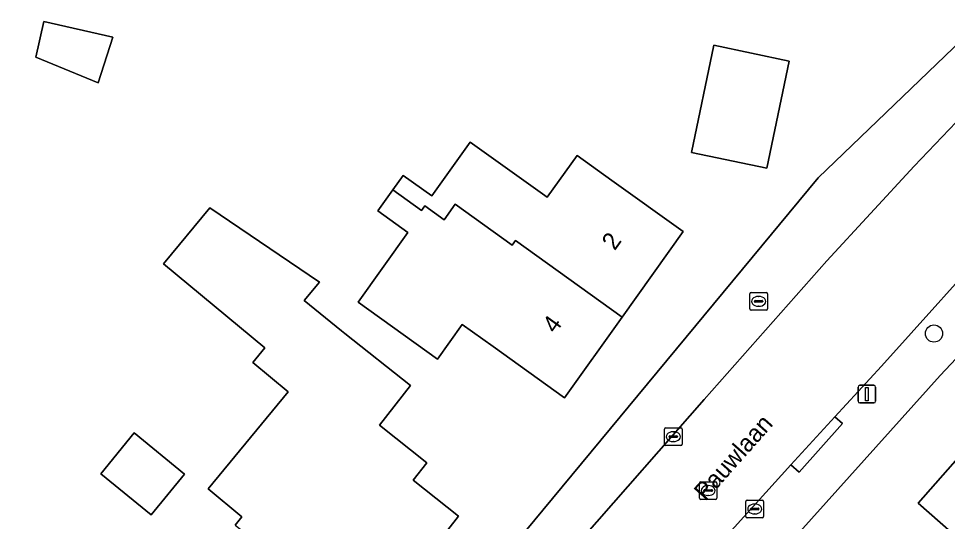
# Model space of a CAD drawing. Extents: x 161772 to 163126, y 383092 to 383917.
# Drawn here: x 162481.4 to 162534.3, y 383587.6 to 383616.2 of the extents above; entities that cross this region are included whole.
import ezdxf

# ---------------------------------------------------------------- set-up
doc = ezdxf.new("R2010")
doc.units = 0
for name, color, linetype in [('IMGEO_Boom', 7, 'Continuous'), ('IMGEO_Brandkraan', 7, 'Continuous'), ('IMGEO_Erf', 7, 'Continuous'), ('IMGEO_Kolk', 7, 'Continuous'), ('IMGEO_Lichtmast', 7, 'Continuous'), ('IMGEO_Openbare_ruimte_label', 7, 'Continuous'), ('IMGEO_Pand', 7, 'Continuous'), ('IMGEO_Pand_nummerreeks', 7, 'Continuous'), ('IMGEO_Rijbaan_lokaal_open', 7, 'Continuous'), ('IMGEO_Rioolput', 7, 'Continuous'), ('IMGEO_Voetpad_open', 7, 'Continuous')]:
    doc.layers.add(name, color=color, linetype=linetype)

msp = doc.modelspace()

# ---------------------------------------------------------------- linework, layer by layer
at = {"layer": 'IMGEO_Boom'}
msp.add_circle((162533.543, 383598.255), 0.489, dxfattribs=at)
at = {"layer": 'IMGEO_Brandkraan'}
for p, q in [((162523.058, 383599.658), (162523.058, 383600.51)), ((162523.133, 383600.584), (162523.985, 383600.584)), ((162523.317, 383600.078), (162523.317, 383600.09)), ((162523.36, 383600.127), (162523.758, 383600.127)), ((162523.546, 383600.364), (162523.571, 383600.364)), ((162523.801, 383600.09), (162523.801, 383600.078)), ((162524.059, 383600.51), (162524.059, 383599.658)), ((162523.985, 383599.584), (162523.133, 383599.584)), ((162523.755, 383600.041), (162523.357, 383600.041)), ((162523.569, 383599.804), (162523.544, 383599.804))]:
    msp.add_line(p, q, dxfattribs=at)
for points in [[(162523.058, 383599.658), (162523.058, 383600.51)], [(162523.133, 383600.584), (162523.985, 383600.584)], [(162524.059, 383600.51), (162524.059, 383599.658)], [(162523.985, 383599.584), (162523.133, 383599.584)]]:
    msp.add_lwpolyline(points, dxfattribs=at)
for centre, radius, start, end in [((162523.135, 383600.508), 0.0765, 91.552, 178.448), ((162523.135, 383600.508), 0.0765, 91.552, 178.448), ((162523.357, 383600.087), 0.0403, 85.8775, 175.7526), ((162523.354, 383600.077), 0.0366, 178.938, 274.7102), ((162523.758, 383600.084), 0.043, 264.8664, 352.4533), ((162523.762, 383600.089), 0.0386, 1.7309, 96.639), ((162523.983, 383600.508), 0.0765, 1.552, 88.448), ((162523.983, 383600.508), 0.0765, 1.552, 88.448), ((162523.135, 383599.66), 0.0765, 181.552, 268.448), ((162523.135, 383599.66), 0.0765, 181.552, 268.448), ((162523.983, 383599.66), 0.0765, 271.552, 358.448), ((162523.983, 383599.66), 0.0765, 271.552, 358.448)]:
    msp.add_arc(centre, radius, start, end, dxfattribs=at)
for centre, major_axis, ratio, start_param, end_param in [((162523.545, 383600.084), (-0.387, 0.002), 0.722429, 4.712389, 7.853982), ((162523.57, 383600.084), (-0.39, 0.002), 0.717154, 1.570796, 4.712389)]:
    msp.add_ellipse(centre, major_axis=major_axis, ratio=ratio, start_param=start_param, end_param=end_param, dxfattribs=at)
at = {"layer": 'IMGEO_Erf'}
for points in [[(162462.704, 383536.779), (162483.744, 383554.98), (162500, 383574.599), (162526.947, 383607.122), (162543.804, 383623.317), (162548.918, 383628.126), (162539.791, 383641.093), (162527.133, 383641.683), (162527.105, 383641.456), (162500, 383642.583), (162442.25, 383644.984), (162375.184, 383528.714), (162418.191, 383500), (162425.357, 383495.215)], [(162493.744, 383587.36), (162494.132, 383587.828), (162492.201, 383589.429), (162496.763, 383594.932), (162494.746, 383596.605), (162495.432, 383597.433), (162489.661, 383602.217), (162492.309, 383605.412), (162498.544, 383601.187), (162497.67, 383600.132), (162499.797, 383598.417), (162500, 383598.256), (162503.741, 383595.297), (162501.958, 383593.04), (162504.664, 383590.902), (162503.885, 383589.916), (162506.472, 383587.872), (162501.403, 383581.38)], [(162539.703, 383602.034), (162533.89, 383595.873), (162525.907, 383586.964), (162518.786, 383578.702), (162510.666, 383568.842), (162501.518, 383557.733), (162500, 383555.89), (162492.693, 383547.017)]]:
    msp.add_lwpolyline(points, dxfattribs=at)
for points in [[(162482.391, 383613.973), (162482.841, 383616.012), (162486.783, 383615.11), (162485.937, 383612.514)], [(162519.734, 383608.563), (162521.016, 383614.659), (162525.306, 383613.757), (162524.024, 383607.661)], [(162502.72, 383606.437), (162503.306, 383607.254), (162504.939, 383606.083), (162507.133, 383609.142), (162511.507, 383606.005), (162513.219, 383608.39), (162515.204, 383606.968), (162519.268, 383604.056), (162515.786, 383599.195), (162512.495, 383594.6), (162508.431, 383597.511), (162506.677, 383598.767), (162505.271, 383596.805), (162500.747, 383600.048), (162503.586, 383604.008), (162501.864, 383605.243)], [(162544.222, 383584.846), (162541.032, 383581.223), (162536.404, 383585.298), (162532.651, 383588.602), (162539.681, 383596.585), (162543.434, 383593.281), (162548.075, 383589.194), (162546.474, 383587.375), (162546.712, 383586.669), (162544.973, 383584.695)], [(162486.087, 383590.277), (162487.992, 383592.607), (162490.859, 383590.263), (162488.955, 383587.933)]]:
    msp.add_lwpolyline(points, close=True, dxfattribs=at)
at = {"layer": 'IMGEO_Kolk'}
for p, q in [((162518.198, 383591.959), (162518.198, 383592.811)), ((162518.273, 383592.885), (162519.125, 383592.885)), ((162519.199, 383592.811), (162519.199, 383591.959)), ((162518.457, 383592.379), (162518.457, 383592.391)), ((162518.895, 383592.342), (162518.497, 383592.342)), ((162518.5, 383592.428), (162518.898, 383592.428)), ((162518.686, 383592.665), (162518.711, 383592.665)), ((162518.941, 383592.391), (162518.941, 383592.379)), ((162519.125, 383591.885), (162518.273, 383591.885)), ((162518.709, 383592.105), (162518.684, 383592.105)), ((162522.835, 383587.848), (162522.835, 383588.7)), ((162522.91, 383588.774), (162523.762, 383588.774)), ((162523.323, 383588.554), (162523.348, 383588.554)), ((162523.836, 383588.7), (162523.836, 383587.848)), ((162523.094, 383588.268), (162523.094, 383588.28)), ((162523.532, 383588.231), (162523.134, 383588.231)), ((162523.137, 383588.317), (162523.535, 383588.317)), ((162523.346, 383587.994), (162523.321, 383587.994)), ((162523.578, 383588.28), (162523.578, 383588.268)), ((162523.762, 383587.774), (162522.91, 383587.774))]:
    msp.add_line(p, q, dxfattribs=at)
for points in [[(162518.198, 383591.959), (162518.198, 383592.811)], [(162518.273, 383592.885), (162519.125, 383592.885)], [(162519.199, 383592.811), (162519.199, 383591.959)], [(162519.125, 383591.885), (162518.273, 383591.885)], [(162522.835, 383587.848), (162522.835, 383588.7)], [(162522.91, 383588.774), (162523.762, 383588.774)], [(162523.836, 383588.7), (162523.836, 383587.848)], [(162523.762, 383587.774), (162522.91, 383587.774)]]:
    msp.add_lwpolyline(points, dxfattribs=at)
for centre, radius, start, end in [((162518.275, 383592.809), 0.0765, 91.552, 178.448), ((162518.275, 383592.809), 0.0765, 91.552, 178.448), ((162519.123, 383592.809), 0.0765, 1.552, 88.448), ((162519.123, 383592.809), 0.0765, 1.552, 88.448), ((162518.497, 383592.388), 0.0403, 85.8775, 175.7526), ((162518.494, 383592.378), 0.0366, 178.938, 274.7102), ((162518.898, 383592.385), 0.043, 264.8664, 352.4533), ((162518.902, 383592.39), 0.0386, 1.7309, 96.639), ((162518.275, 383591.961), 0.0765, 181.552, 268.448), ((162518.275, 383591.961), 0.0765, 181.552, 268.448), ((162519.123, 383591.961), 0.0765, 271.552, 358.448), ((162519.123, 383591.961), 0.0765, 271.552, 358.448), ((162522.912, 383588.698), 0.0765, 91.552, 178.448), ((162522.912, 383588.698), 0.0765, 91.552, 178.448), ((162523.76, 383588.698), 0.0765, 1.552, 88.448), ((162523.76, 383588.698), 0.0765, 1.552, 88.448), ((162523.134, 383588.277), 0.0403, 85.8775, 175.7526), ((162523.131, 383588.267), 0.0366, 178.938, 274.7102), ((162523.535, 383588.274), 0.043, 264.8664, 352.4533), ((162523.539, 383588.279), 0.0386, 1.7309, 96.639), ((162522.912, 383587.85), 0.0765, 181.552, 268.448), ((162522.912, 383587.85), 0.0765, 181.552, 268.448), ((162523.76, 383587.85), 0.0765, 271.552, 358.448), ((162523.76, 383587.85), 0.0765, 271.552, 358.448)]:
    msp.add_arc(centre, radius, start, end, dxfattribs=at)
for centre, major_axis, ratio, start_param, end_param in [((162518.685, 383592.385), (-0.387, 0.002), 0.722429, 4.712389, 7.853982), ((162518.71, 383592.385), (-0.39, 0.002), 0.717154, 1.570796, 4.712389), ((162523.322, 383588.274), (-0.387, 0.002), 0.722429, 4.712389, 7.853982), ((162523.347, 383588.274), (-0.39, 0.002), 0.717154, 1.570796, 4.712389)]:
    msp.add_ellipse(centre, major_axis=major_axis, ratio=ratio, start_param=start_param, end_param=end_param, dxfattribs=at)
at = {"layer": 'IMGEO_Lichtmast'}
for p, q in [((162529.226, 383594.41), (162529.226, 383595.21)), ((162529.226, 383595.21), (162529.226, 383594.41)), ((162529.326, 383595.31), (162530.116, 383595.31)), ((162530.116, 383595.31), (162529.326, 383595.31)), ((162530.216, 383595.21), (162530.216, 383594.41)), ((162530.216, 383594.41), (162530.216, 383595.21)), ((162530.116, 383594.31), (162529.326, 383594.31)), ((162529.326, 383594.31), (162530.116, 383594.31))]:
    msp.add_line(p, q, dxfattribs=at)
msp.add_lwpolyline([(162529.646, 383595.185), (162529.796, 383595.185), (162529.796, 383594.435), (162529.646, 383594.435), (162529.646, 383595.185)], dxfattribs=at)
for centre, start, end in [((162529.326, 383595.21), 90, 180), ((162529.326, 383595.21), 90, 180), ((162530.116, 383595.21), 0, 90), ((162530.116, 383595.21), 360, 90), ((162529.326, 383594.41), 180, 270), ((162529.326, 383594.41), 180, 270), ((162530.116, 383594.41), 270, 0), ((162530.116, 383594.41), 270, 0)]:
    msp.add_arc(centre, 0.1, start, end, dxfattribs=at)
at = {"layer": 'IMGEO_Pand'}
for points in [[(162482.391, 383613.973), (162485.937, 383612.514), (162486.783, 383615.11), (162482.841, 383616.012)], [(162524.024, 383607.661), (162525.306, 383613.757), (162521.016, 383614.659), (162519.734, 383608.563)], [(162502.72, 383606.437), (162504.356, 383605.265), (162504.544, 383605.528), (162505.651, 383604.734), (162506.277, 383605.609), (162509.517, 383603.287), (162509.705, 383603.55), (162515.786, 383599.195), (162519.268, 383604.056), (162515.204, 383606.968), (162513.219, 383608.39), (162511.507, 383606.005), (162507.133, 383609.142), (162504.939, 383606.083), (162503.306, 383607.254)], [(162502.72, 383606.437), (162501.864, 383605.243), (162503.586, 383604.008), (162500.747, 383600.048), (162505.271, 383596.805), (162506.677, 383598.767), (162508.431, 383597.511), (162512.495, 383594.6), (162515.786, 383599.195), (162509.705, 383603.55), (162509.517, 383603.287), (162506.277, 383605.609), (162505.651, 383604.734), (162504.544, 383605.528), (162504.356, 383605.265)], [(162504.664, 383590.902), (162501.958, 383593.04), (162503.741, 383595.297), (162500, 383598.256), (162499.797, 383598.417), (162497.67, 383600.132), (162498.544, 383601.187), (162492.309, 383605.412), (162489.661, 383602.217), (162495.432, 383597.433), (162494.746, 383596.605), (162496.763, 383594.932), (162492.201, 383589.429), (162494.132, 383587.828), (162493.744, 383587.36), (162494.073, 383587.101), (162500, 383582.475), (162501.06, 383581.651), (162501.403, 383581.38), (162506.472, 383587.872), (162503.885, 383589.916)], [(162541.032, 383581.223), (162544.222, 383584.846), (162544.973, 383584.695), (162546.712, 383586.669), (162546.474, 383587.375), (162548.075, 383589.194), (162543.434, 383593.281), (162539.681, 383596.585), (162532.651, 383588.602), (162536.404, 383585.298)], [(162490.859, 383590.263), (162487.992, 383592.607), (162486.087, 383590.277), (162488.955, 383587.933)]]:
    msp.add_lwpolyline(points, close=True, dxfattribs=at)
at = {"layer": 'IMGEO_Rijbaan_lokaal_open'}
msp.add_lwpolyline([(162537.203, 383612.786), (162532.418, 383607.776), (162527.435, 383602.384), (162520.458, 383594.506), (162513.52, 383586.607), (162511.095, 383583.664), (162507.749, 383579.508), (162503.132, 383574.038), (162499.96, 383570.06), (162490.713, 383558.838), (162488.243, 383555.841), (162487.591, 383555.051), (162492.315, 383551.109), (162499.866, 383560.331), (162506.576, 383568.47), (162512.205, 383575.261), (162517.639, 383581.965), (162521.297, 383586.253), (162525.402, 383590.777), (162527.89, 383593.519), (162530.565, 383596.403), (162537.488, 383604.096)], dxfattribs=at)
at = {"layer": 'IMGEO_Rioolput'}
for p, q in [((162520.184, 383588.895), (162520.184, 383589.747)), ((162520.259, 383589.821), (162521.111, 383589.821)), ((162520.672, 383589.601), (162520.697, 383589.601)), ((162521.185, 383589.747), (162521.185, 383588.895)), ((162520.443, 383589.315), (162520.443, 383589.327)), ((162520.881, 383589.278), (162520.483, 383589.278)), ((162520.486, 383589.364), (162520.884, 383589.364)), ((162520.695, 383589.041), (162520.67, 383589.041)), ((162520.927, 383589.327), (162520.927, 383589.315)), ((162521.111, 383588.821), (162520.259, 383588.821))]:
    msp.add_line(p, q, dxfattribs=at)
for points in [[(162520.184, 383588.895), (162520.184, 383589.747)], [(162520.259, 383589.821), (162521.111, 383589.821)], [(162521.185, 383589.747), (162521.185, 383588.895)], [(162521.111, 383588.821), (162520.259, 383588.821)]]:
    msp.add_lwpolyline(points, dxfattribs=at)
for centre, radius, start, end in [((162520.261, 383589.745), 0.0765, 91.552, 178.448), ((162520.261, 383589.745), 0.0765, 91.552, 178.448), ((162521.109, 383589.745), 0.0765, 1.552, 88.448), ((162521.109, 383589.745), 0.0765, 1.552, 88.448), ((162520.483, 383589.324), 0.0403, 85.8775, 175.7526), ((162520.48, 383589.314), 0.0366, 178.938, 274.7102), ((162520.884, 383589.321), 0.043, 264.8664, 352.4533), ((162520.888, 383589.326), 0.0386, 1.7309, 96.639), ((162520.261, 383588.897), 0.0765, 181.552, 268.448), ((162520.261, 383588.897), 0.0765, 181.552, 268.448), ((162521.109, 383588.897), 0.0765, 271.552, 358.448), ((162521.109, 383588.897), 0.0765, 271.552, 358.448)]:
    msp.add_arc(centre, radius, start, end, dxfattribs=at)
for centre, major_axis, ratio, start_param, end_param in [((162520.671, 383589.321), (-0.387, 0.002), 0.722429, 4.712389, 7.853982), ((162520.696, 383589.321), (-0.39, 0.002), 0.717154, 1.570796, 4.712389)]:
    msp.add_ellipse(centre, major_axis=major_axis, ratio=ratio, start_param=start_param, end_param=end_param, dxfattribs=at)
at = {"layer": 'IMGEO_Voetpad_open'}
for points in [[(162549.66, 383629.858), (162548.918, 383628.126), (162543.804, 383623.317), (162526.947, 383607.122), (162500, 383574.599), (162483.744, 383554.98), (162462.704, 383536.779), (162467.807, 383530.859), (162432.045, 383500), (162426.613, 383495.312), (162428.778, 383494.029), (162435.72, 383500), (162437.045, 383501.14), (162437.192, 383501.282), (162438.691, 383502.574), (162438.438, 383502.865), (162441.394, 383505.425), (162441.654, 383505.126), (162443.112, 383506.379), (162469.395, 383528.971)], [(162468.577, 383537.721), (162484.483, 383551.467), (162485.735, 383552.822), (162487.591, 383555.051), (162488.243, 383555.841), (162487.915, 383556.108), (162490.371, 383559.116), (162490.713, 383558.838), (162499.96, 383570.06), (162503.132, 383574.038), (162507.749, 383579.508), (162511.095, 383583.664), (162510.859, 383583.859), (162513.286, 383586.801), (162513.52, 383586.607), (162520.458, 383594.506), (162527.435, 383602.384), (162532.418, 383607.776), (162537.203, 383612.786), (162540.103, 383615.776), (162538.984, 383617.258), (162540.462, 383618.813), (162542.308, 383616.755)], [(162497.729, 383541.518), (162492.693, 383547.017), (162500, 383555.89), (162501.518, 383557.733), (162510.666, 383568.842), (162518.786, 383578.702), (162525.907, 383586.964), (162533.89, 383595.873), (162539.703, 383602.034), (162537.488, 383604.096), (162530.565, 383596.403), (162527.89, 383593.519), (162528.327, 383593.13), (162525.868, 383590.36), (162525.402, 383590.777), (162521.297, 383586.253), (162517.639, 383581.965), (162512.205, 383575.261), (162506.576, 383568.47), (162499.866, 383560.331), (162492.315, 383551.109), (162490.534, 383548.934), (162490.049, 383548.342)]]:
    msp.add_lwpolyline(points, dxfattribs=at)
msp.add_lwpolyline([(162528.327, 383593.13), (162527.89, 383593.519), (162525.402, 383590.777), (162525.868, 383590.36)], close=True, dxfattribs=at)

# ---------------------------------------------------------------- texts
at = {"layer": 'IMGEO_Openbare_ruimte_label'}
msp.add_text('Pauwlaan', height=1, rotation=48.4045, dxfattribs=at).set_placement((162520.535, 383588.688))
at = {"layer": 'IMGEO_Pand_nummerreeks'}
for s, p in [('2', (162515.364, 383602.934)), ('4', (162511.98, 383598.208))]:
    msp.add_text(s, height=1, rotation=54.3873, dxfattribs=at).set_placement(p)

doc.saveas('drawing.dxf')
